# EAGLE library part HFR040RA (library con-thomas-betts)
THOMAS&BETTS
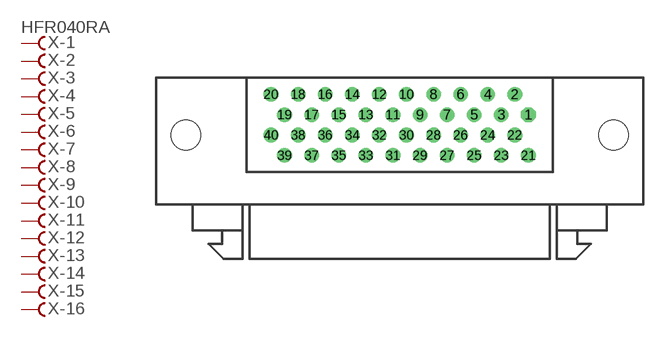
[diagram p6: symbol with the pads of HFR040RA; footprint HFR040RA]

Designator prefix X; gates -1=FV -2=F -3=F -4=F -5=F -6=F -7=F -8=F -9=F -10=F -11=F -12=F -13=F -14=F -15=F -16=F -17=F -18=F -19=F -20=F -21=F -22=F -23=F -24=F -25=F -26=F -27=F -28=F -29=F -30=F -31=F -32=F -33=F -34=F -35=F -36=F -37=F -38=F -39=F -40=F

## HFR040RA (OC_FARNELL: unknown; OC_NEWARK: unknown)  [HFR040RA]
1  -1:F  pas
2  -2:F  pas
3  -3:F  pas
4  -4:F  pas
5  -5:F  pas
6  -6:F  pas
7  -7:F  pas
8  -8:F  pas
9  -9:F  pas
10  -10:F  pas
11  -11:F  pas
12  -12:F  pas
13  -13:F  pas
14  -14:F  pas
15  -15:F  pas
16  -16:F  pas
17  -17:F  pas
18  -18:F  pas
19  -19:F  pas
20  -20:F  pas
21  -21:F  pas
22  -22:F  pas
23  -23:F  pas
24  -24:F  pas
25  -25:F  pas
26  -26:F  pas
27  -27:F  pas
28  -28:F  pas
29  -29:F  pas
30  -30:F  pas
31  -31:F  pas
32  -32:F  pas
33  -33:F  pas
34  -34:F  pas
35  -35:F  pas
36  -36:F  pas
37  -37:F  pas
38  -38:F  pas
39  -39:F  pas
40  -40:F  pas

## Footprint HFR040RA (pad centres in mm)
THOMAS&BETTS Fine Pitch "D" Connector HFR040RA29xxx
drill 0.864 octagon: 1 12.065,6.98
drill 0.864 round: 2 10.795,8.89; 3 9.525,6.98; 4 8.255,8.89; 5 6.985,6.98; 6 5.715,8.89; 7 4.445,6.98; 8 3.175,8.89; 9 1.905,6.98; 10 0.635,8.89; 11 -0.635,6.98; 12 -1.905,8.89; 13 -3.175,6.98; 14 -4.445,8.89; 15 -5.715,6.98; 16 -6.985,8.89; 17 -8.255,6.98; 18 -9.525,8.89; 19 -10.795,6.98; 20 -12.065,8.89; 21 12.065,3.16; 22 10.795,5.07; 23 9.525,3.16; 24 8.255,5.07; 25 6.985,3.16; 26 5.715,5.07; 27 4.445,3.16; 28 3.175,5.07; 29 1.905,3.16; 30 0.635,5.07; 31 -0.635,3.16; 32 -1.905,5.07; 33 -3.175,3.16; 34 -4.445,5.07; 35 -5.715,3.16; 36 -6.985,5.07; 37 -8.255,3.16; 38 -9.525,5.07; 39 -10.795,3.16; 40 -12.065,5.07
hole 2.769 at 20.066,5.07
hole 2.769 at -20.066,5.07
